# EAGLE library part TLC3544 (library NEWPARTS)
A/D CONVERTER
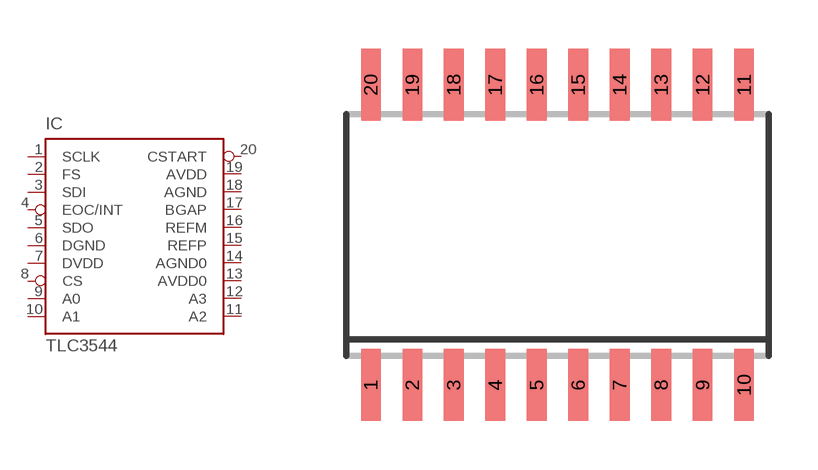
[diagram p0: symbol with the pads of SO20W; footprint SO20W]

Designator prefix IC

## TLC3544D  [SO20W]
1  SCLK  pwr
2  FS  out
3  SDI  in
4  EOC/INT  in
5  SDO  in
6  DGND  in
7  DVDD  in
8  CS  in
9  A0  in
10  A1  in
11  A2  in
12  A3  in
13  AVDD0  pwr
14  AGND0  pwr
15  REFP  out
16  REFM  hiz
17  BGAP  in
18  AGND  in
19  AVDD  in
20  CSTART  in

## Footprint SO20W (pad centres in mm)
Small Outline Package 20 wide
smd 0.6 x 2.2: 1 -5.715,-4.6; 2 -4.445,-4.6; 3 -3.175,-4.6; 4 -1.905,-4.6; 5 -0.635,-4.6; 6 0.635,-4.6; 7 1.905,-4.6; 8 3.175,-4.6; 9 4.445,-4.6; 10 5.715,-4.6; 11 5.715,4.6; 12 4.445,4.6; 13 3.175,4.6; 14 1.905,4.6; 15 0.635,4.6; 16 -0.635,4.6; 17 -1.905,4.6; 18 -3.175,4.6; 19 -4.445,4.6; 20 -5.715,4.6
